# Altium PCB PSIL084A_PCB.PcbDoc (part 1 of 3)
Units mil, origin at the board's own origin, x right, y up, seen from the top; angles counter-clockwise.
Board outline 8750 x 2700 mil, 4 copper layers (Top Layer, Signal Layer 1, Signal Layer 2, Bottom Layer), stack 61.2 mil thick; 274 components, 214 nets, 1279 pads, 354 vias.
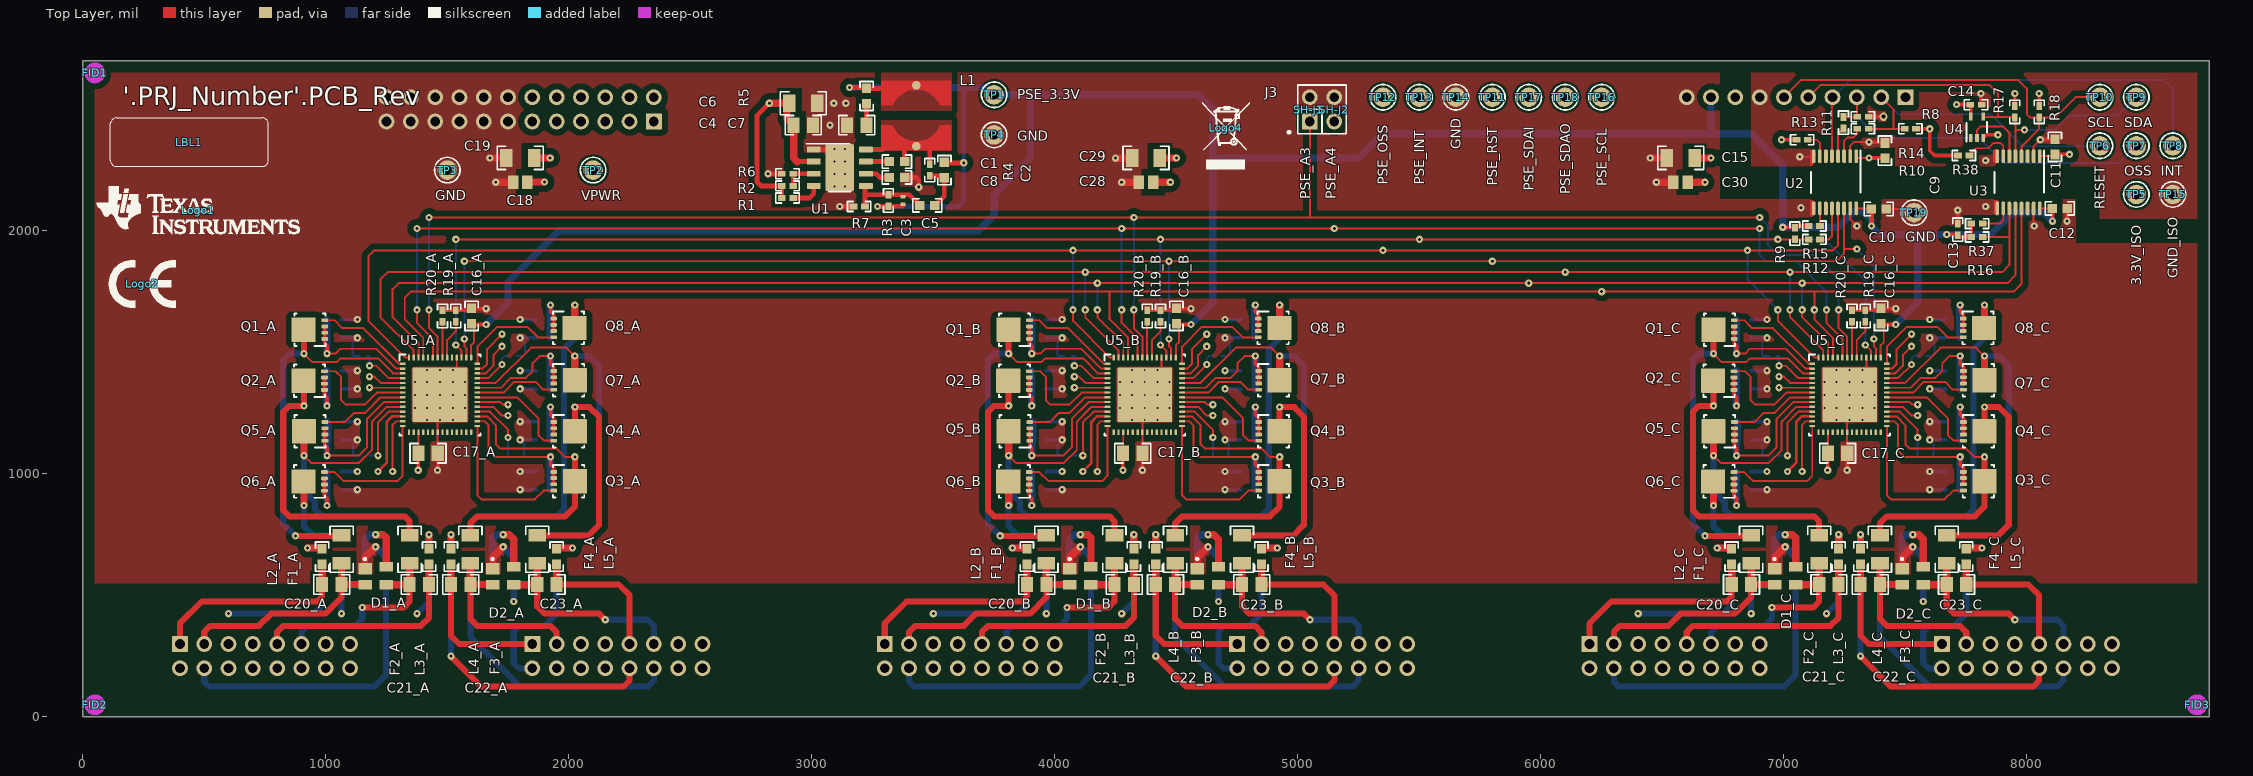
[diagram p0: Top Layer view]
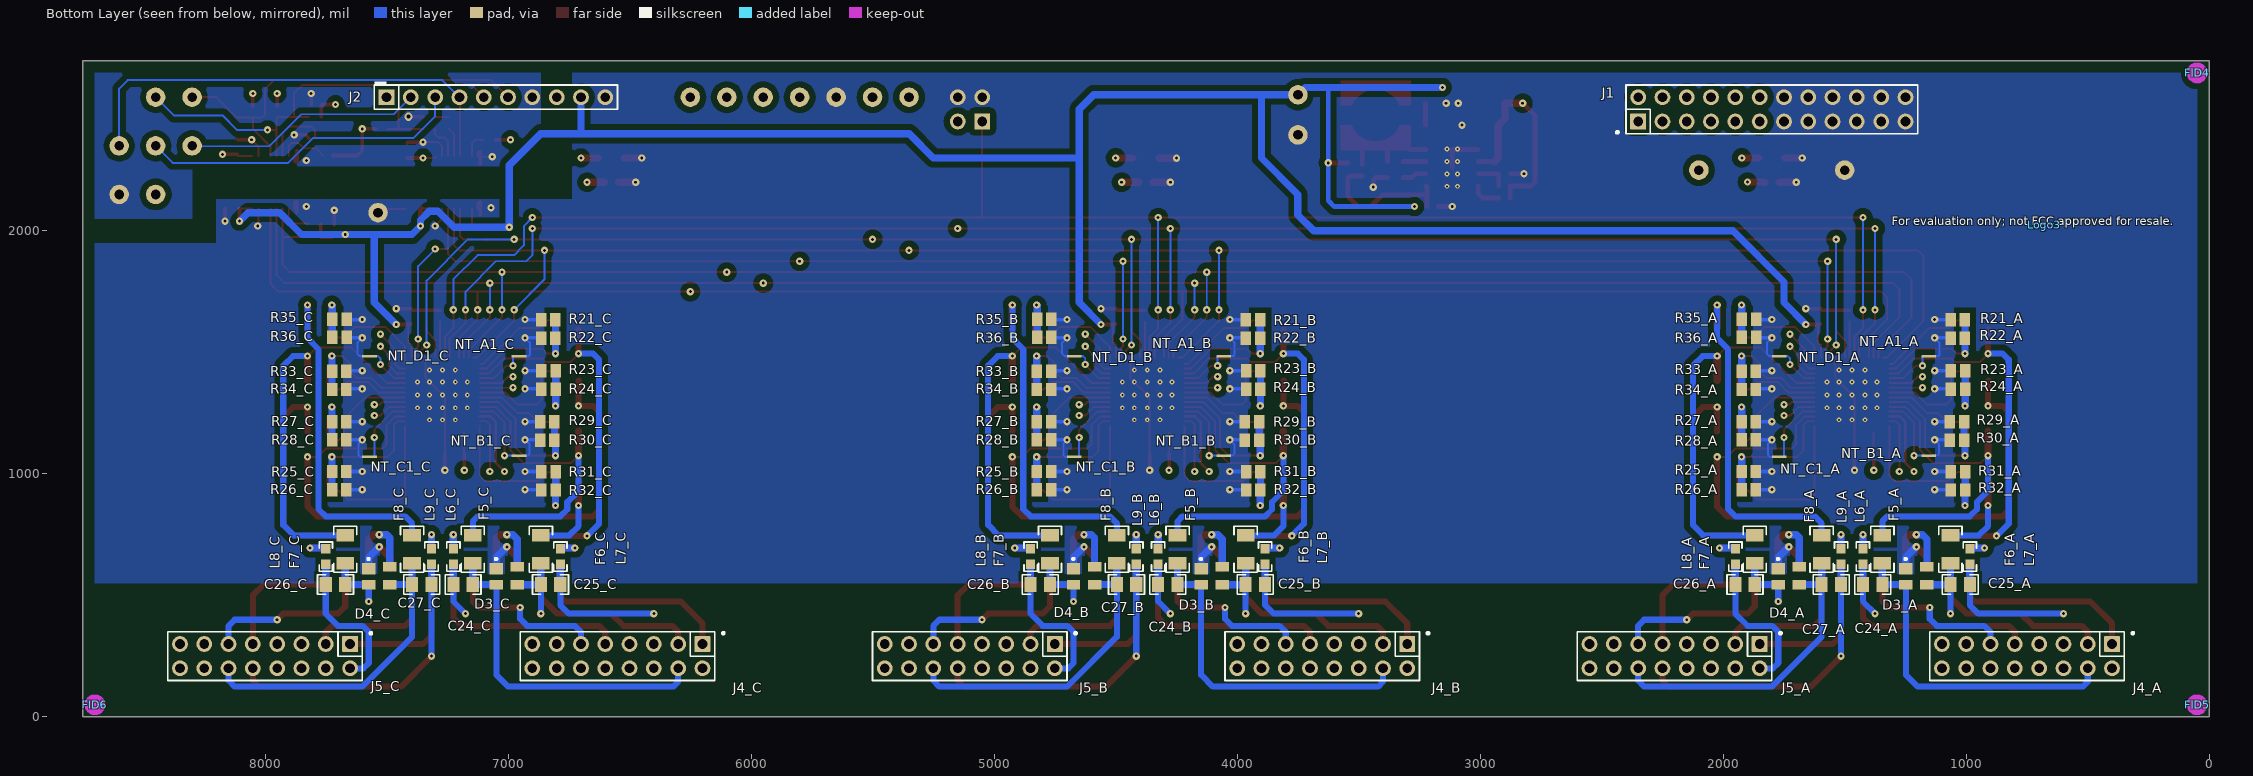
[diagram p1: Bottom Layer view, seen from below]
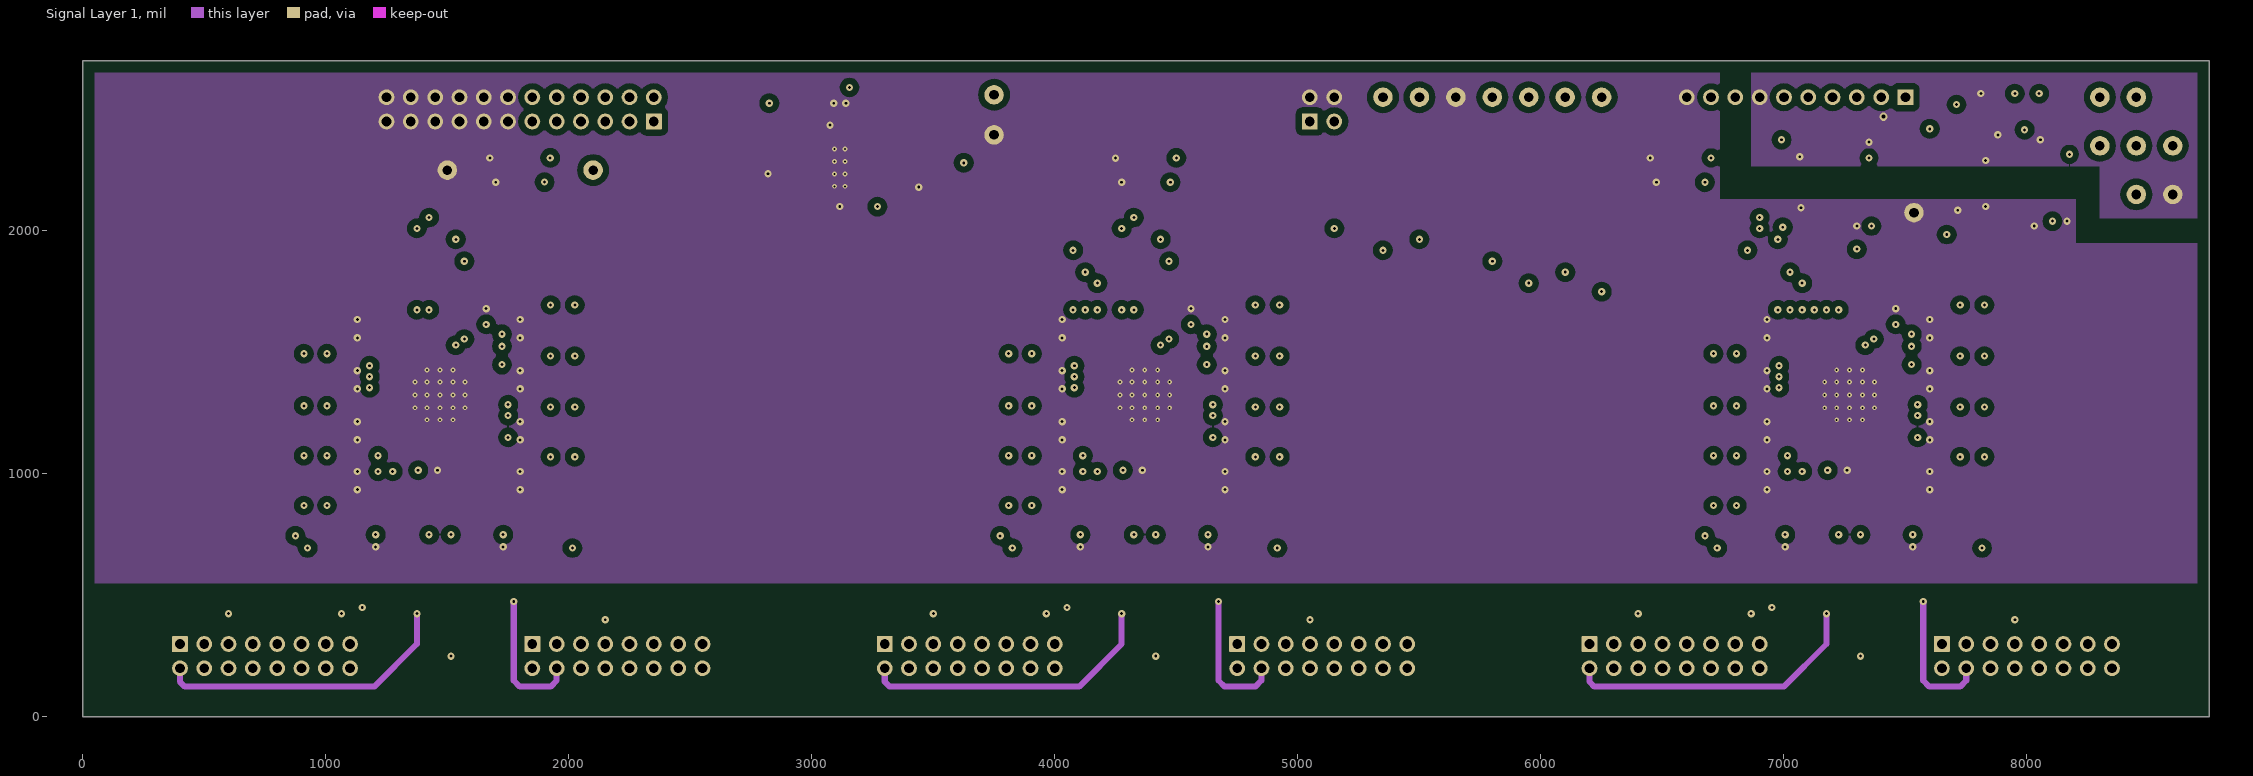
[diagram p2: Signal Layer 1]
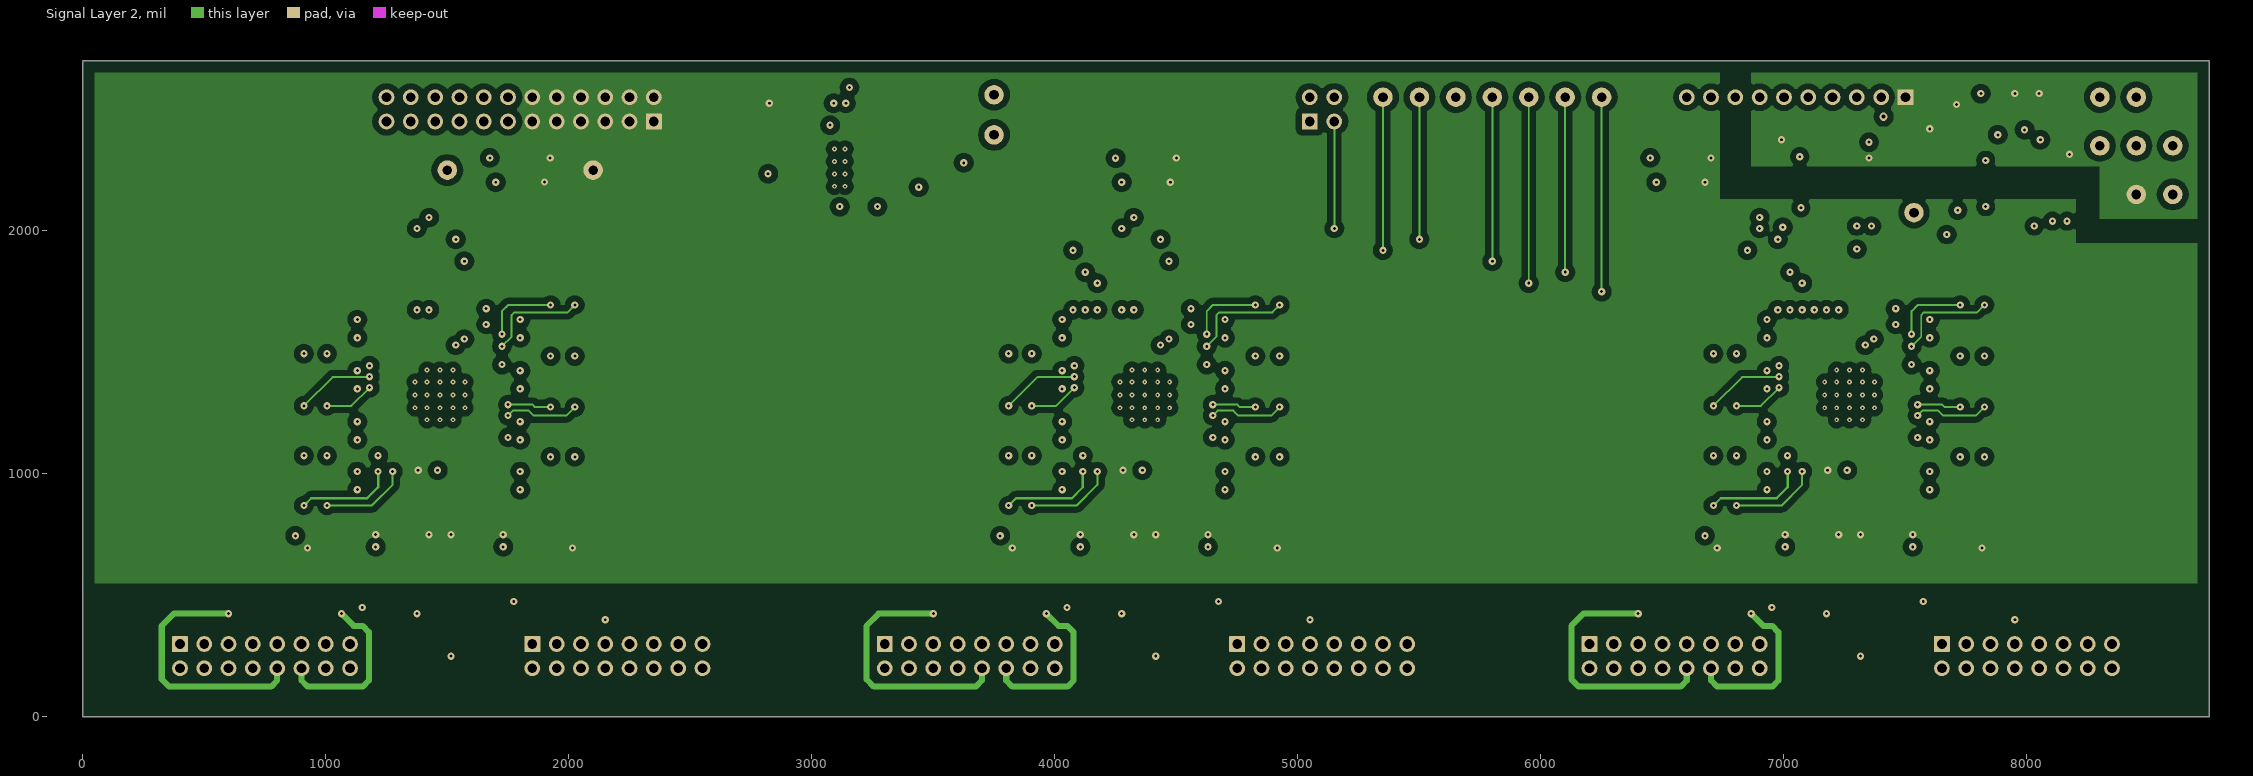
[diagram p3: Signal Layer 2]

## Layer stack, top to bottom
Top Solder: solder mask 0.4, Solder Resist, Dk 3.5
Top Layer: signal copper 2.8
Dielectric1: prepreg 10, FR-4 High TG, Dk 4.2
Signal Layer 1: signal copper 2.8
Dielectric 2: core 30, FR-4 High TG, Dk 4.2
Signal Layer 2: signal copper 2.8
Dielectric 3: prepreg 10, FR-4 High TG, Dk 4.2
Bottom Layer: signal copper 2.8
Bottom Solder: solder mask 0.4, Solder Resist, Dk 3.5

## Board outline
0,0 8750,0 8750,2700 0,2700

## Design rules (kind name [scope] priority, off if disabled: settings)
AcuteAngle [All] p1: minimum=4.50000000000000E+0001 checktracksonly=FALSE
AssemblyTestPointUsage [All] p1: valid=2
BoardOutlineClearance BoardOutlineClearance_MountingHoles [OnCopper and InComponentClass('Mounting Holes')] p1: gap=40 ignorepadtopadclearanceinfootprint=FALSE
BoardOutlineClearance BoardOutlineClearance_Poly [OnCopper and IsPoly] p2: gap=25 ignorepadtopadclearanceinfootprint=FALSE
BoardOutlineClearance [OnCopper and Not InComponentClass('Logo') and not InComponentClass('FiducialMark') and not InRegion(1000,500,4000,800) and not InPoly] p3: gap=75 ignorepadtopadclearanceinfootprint=FALSE
Clearance Clearance_Keepouts [((IsTrack Or IsArc) And Not InPoly) And IsFree and IsKeepOut vs ((IsTrack Or IsArc) And Not InPoly) And IsFree and IsKeepOut] p1: gap=0 ignorepadtopadclearanceinfootprint=FALSE
Clearance Clearance_Poly [InPolygon] p2: gap=25 ignorepadtopadclearanceinfootprint=FALSE except(0: Arc-Hole Track-Hole SMDPad-Hole THPad-Hole Via-Hole Fill-Hole Poly-Hole Region-Hole Text-Hole)
Clearance Clearance_FiducialMark [IsKeepOut and InComponentClass('FiducialMark') vs IsPad and InComponentClass('FiducialMark')] p3: gap=0 ignorepadtopadclearanceinfootprint=FALSE
Clearance [All] p4: gap=7.87 ignorepadtopadclearanceinfootprint=FALSE except(0: Arc-Hole Track-Hole SMDPad-Hole THPad-Hole Via-Hole Fill-Hole Poly-Hole Region-Hole Text-Hole)
ComponentClearance ComponentClearance_MountingHoles_FiducialMarks [InComponentClass('Mounting Holes') vs InComponentClass('FiducialMark')] p1: gap=50 collisioncheckmode=3 verticalgap=10 showdistances=FALSE
ComponentClearance ComponentClearance_Shunt [InComponentClass('Header') or InComponentClass('Shunt') vs InComponentClass('Shunt')] p2: gap=0 collisioncheckmode=3 verticalgap=0 showdistances=FALSE
ComponentClearance ComponentClearance_Logo [InComponentClass('Logo')] p3: gap=50 collisioncheckmode=3 verticalgap=10 showdistances=FALSE
ComponentClearance ComponentClearance_ScrewToNut [(HasFootprint('NY PMS 440 0025 PH')) vs (HasFootprint('Keystone_1902C'))] p4: gap=5 collisioncheckmode=3 verticalgap=10 showdistances=FALSE
ComponentClearance ComponentClearance_MountingHoles [InComponentClass('Mounting Holes')] p5: gap=250 collisioncheckmode=3 verticalgap=100000 showdistances=FALSE
ComponentClearance ComponentClearance_SmallPassives [HasFootprint('0201*') or HasFootprint('0402*') or HasFootprint('0508') or HasFootprint('0603*') or HasFootprint('0612') or HasFootprint('0805*') or HasFootprint('0815*') or HasFootprint('0830*') or HasFootprint('1206*') or HasFootprint('1210*') or HasFootprint('1808*') or HasFootprint('1812*') or HasFootprint('1825*') or HasFootprint('2010*') or HasFootprint('2220*') or HasFootprint('2225*') or HasFootprint('2512*') or HasFootprint('2728*') or HasFootprint('3518*') vs HasFootprint('0201*') or HasFootprint('0402*') or HasFootprint('0508') or HasFootprint('0603*') or HasFootprint('0612') or HasFootprint('0805*') or HasFootprint('0815*') or HasFootprint('0830*') or HasFootprint('1206*') or HasFootprint('1210*') or HasFootprint('1808*') or HasFootprint('1812*') or HasFootprint('1825*') or HasFootprint('2010*') or HasFootprint('2220*') or HasFootprint('2225*') or HasFootprint('2512*') or HasFootprint('2728*') or HasFootprint('3518*')] p6: gap=14.96 collisioncheckmode=3 verticalgap=10 showdistances=FALSE
ComponentClearance ComponentClearance_THtoSMT [IsThruComponent vs IsSMTComponent] p7: gap=40 collisioncheckmode=3 verticalgap=30 showdistances=FALSE
ComponentClearance ComponentClearance_THtoTH [IsThruComponent vs IsThruComponent] p8: gap=30 collisioncheckmode=3 verticalgap=30 showdistances=FALSE
ComponentClearance [All] p9: gap=30 collisioncheckmode=3 verticalgap=10 showdistances=FALSE
DiffPairsRouting [All] p1: maxlimit=100 minlimit=10 mostfreqgap=10 toplayer_minwidth=15 toplayer_maxwidth=15 toplayer_prefwidth=15 midlayer1_minwidth=15 midlayer1_maxwidth=15 midlayer1_prefwidth=15 midlayer2_minwidth=15 midlayer2_maxwidth=15 midlayer2_prefwidth=15 bottomlayer_minwidth=15 bottomlayer_maxwidth=15 bottomlayer_prefwidth=15 maxuncoupledlength=1000
FabricationTestPointUsage TestPointUsage [All] p1: valid=2 allowmultiple=FALSE
FabricationTestpoint Testpoint [All] p1: side=3 testpointundercomponent=TRUE minsize=40 maxsize=100 preferedsize=60 minholesize=0 maxholesize=40 preferedholesize=32 testpointgrid=1 allowsidetop=TRUE allowsidebottom=TRUE usegrid=TRUE gridtolerance=0.01
FanoutControl Fanout_LCC [IsLCC] p1: bgadir=Out bgaviamode=Centered fanoutstyle=Auto fanoutdirection=Alternating viagrid=1 // Fanout_LCC (Default Rule)
FanoutControl Fanout_BGA [IsBGA] p2: bgadir=Out bgaviamode=Centered fanoutstyle=Auto fanoutdirection=Alternating viagrid=1 // Fanout_BGA (Default Rule)
FanoutControl Fanout_Default [All] p4: bgadir=Out bgaviamode=Centered fanoutstyle=Auto fanoutdirection=Alternating viagrid=1 // Fanout_Default (Default Rule)
FanoutControl Fanout_Small [(CompPinCount < 5)] p5: bgadir=Out bgaviamode=Centered fanoutstyle=Auto fanoutdirection=OutThenIn viagrid=1 // Fanout_Small (Default Rule)
Height [All] p1: minheight=0 maxheight=2000 prefheight=500
HoleSize [All] p1: absolutevalues=TRUE maxlimit=251 minlimit=7.87 maxpercent=80.000 minpercent=20.000
MinimumAnnularRing MinimumAnnularRing_ThermalPadVias [IsVia and InAnyComponent] p1: minimumring=5.91
MinimumAnnularRing [All] p2: minimumring=8
MinimumSolderMaskSliver MinimumSolderMaskSliver_Logo [InComponentClass('Logo') vs InComponentClass('Logo')] p1: minsoldermaskwidth=0.7
MinimumSolderMaskSliver [All] p2: minsoldermaskwidth=3.94
PlaneConnect [All] p1: planeconnectstyle=Relief reliefexpansion=10 reliefentries=4 reliefconductorwidth=10 reliefairgap=10
PolygonConnect [All] p1: connectstyle=Direct reliefconductorwidth=10 reliefentries=4 polygonreliefangle="90 Angle" airgapwidth=10
RoomDefinition B [InComponentClass('B')] p1: confinementstyle=ConfineIn formatcopy=TRUE lockcomponents=FALSE outline 3200,100 5550,100 5550,1800 3200,1800
RoomDefinition C [InComponentClass('C')] p2: confinementstyle=ConfineIn formatcopy=TRUE lockcomponents=FALSE outline 6100,100 8450,100 8450,1800 6100,1800
RoomDefinition A [InComponentClass('A')] p3: confinementstyle=ConfineIn formatcopy=TRUE lockcomponents=FALSE outline 300,100 2650,100 2650,1800 300,1800
RoutingVias ThermalPadVias [IsVia and InAnyComponent] p1: holewidth=7.87 width=19.68 viastyle="Through Hole" minholewidth=7.87 minwidth=19.68 maxholewidth=12.99 maxwidth=23.62
RoutingVias [All] p2: holewidth=12 width=30 viastyle="Through Hole" minholewidth=7.87 minwidth=26 maxholewidth=40 maxwidth=65
SilkToBoardRegionClearance [Not ((IsComment or IsDesignator) And (Hide <> 'False')) and not InRegion(1000,500,4000,800)] p1:
SilkToSilkClearance SilkToSilkClearance_Pb-FreeLogo [(HasFootprint('Pb-Free_Overlay_Medium') OR HasFootprint('Pb-Free_Overlay_Small')) vs (HasFootprint('Pb-Free_Overlay_Medium') OR HasFootprint('Pb-Free_Overlay_Small'))] p1: silktosilkclearance=0
SilkToSilkClearance [All] p2: silktosilkclearance=4
SilkToSolderMaskClearance SilkToComponentPadClearance [(IsPad or IsFill or IsRegion) and InAnycomponent] p1: minsilkscreentomaskgap=5 clearancetoexposedcopper=TRUE
SilkToSolderMaskClearance "Silk to Solder Mask Opening" [All] p2: minsilkscreentomaskgap=4 clearancetoexposedcopper=FALSE
SolderMaskExpansion [All] p1: expansion=1.97
Width [All] p1: maxlimit=100 minlimit=6 preferedwidth=10 checkconnectedcopper=TRUE
14 further rules are at their usual default settings.

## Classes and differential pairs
channel class PSIL084A_SH2: A B C
component class U_PSIL084A_EVM_Hardware: !PCB FID1 FID2 FID3 FID4 FID5 FID6 LBL1 Logo1 Logo2 Logo3 Logo4 SH-J1 SH-J2 ZZ1 ZZ2 ZZ3 ZZ4 ZZ5
component class Logo: Logo1
component class Label: LBL1
component class FiducialMark: FID1 FID2 FID3 FID4 FID5 FID6
component class AssemblyNote: ZZ1 ZZ2 ZZ3 ZZ4 ZZ5
component class A: C16_A C17_A C20_A C21_A C22_A C23_A C24_A C25_A C26_A C27_A D1_A D2_A D3_A D4_A F1_A F2_A F3_A F4_A F5_A F6_A F7_A F8_A J4_A J5_A L2_A L3_A L4_A L5_A L6_A L7_A L8_A L9_A NT_A1_A NT_B1_A NT_C1_A NT_D1_A Q1_A Q2_A Q3_A Q4_A Q5_A Q6_A Q7_A Q8_A R19_A R20_A R21_A R22_A R23_A R24_A R25_A R26_A R27_A R28_A R29_A R30_A R31_A R32_A R33_A R34_A R35_A R36_A U5_A
component class B: C16_B C17_B C20_B C21_B C22_B C23_B C24_B C25_B C26_B C27_B D1_B D2_B D3_B D4_B F1_B F2_B F3_B F4_B F5_B F6_B F7_B F8_B J4_B J5_B L2_B L3_B L4_B L5_B L6_B L7_B L8_B L9_B NT_A1_B NT_B1_B NT_C1_B NT_D1_B Q1_B Q2_B Q3_B Q4_B Q5_B Q6_B Q7_B Q8_B R19_B R20_B R21_B R22_B R23_B R24_B R25_B R26_B R27_B R28_B R29_B R30_B R31_B R32_B R33_B R34_B R35_B R36_B U5_B
component class C: C16_C C17_C C20_C C21_C C22_C C23_C C24_C C25_C C26_C C27_C D1_C D2_C D3_C D4_C F1_C F2_C F3_C F4_C F5_C F6_C F7_C F8_C J4_C J5_C L2_C L3_C L4_C L5_C L6_C L7_C L8_C L9_C NT_A1_C NT_B1_C NT_C1_C NT_D1_C Q1_C Q2_C Q3_C Q4_C Q5_C Q6_C Q7_C Q8_C R19_C R20_C R21_C R22_C R23_C R24_C R25_C R26_C R27_C R28_C R29_C R30_C R31_C R32_C R33_C R34_C R35_C R36_C U5_C
component class Header: J1 J2 J3 J4_A J4_B J4_C J5_A J5_B J5_C
component class PSIL084A_SH1: C1 C2 C3 C4 C5 C6 C7 C8 C9 C10 C11 C12 C13 C14 C15 C18 C19 C28 C29 C30 J1 J2 J3 L1 R1 R2 R3 R4 R5 R6 R7 R8 R9 R10 R11 R12 R13 R14 R15 R16 R17 R18 R37 R38 TP1 TP2 TP3 TP4 TP5 TP6 TP7 TP8 TP9 TP10 TP11 TP12 TP13 TP14 TP15 TP16 TP17 TP18 TP19 U1 U2 U3 U4
component class Shunt: SH-J1 SH-J2

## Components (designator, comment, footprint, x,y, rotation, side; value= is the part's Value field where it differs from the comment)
C1 "885012206089" 0603 3350,2285 r180 top value=0.01uF
C2 "GRM1885C1H332JA01D" 0603 3545,2250 r270 top value=3300pF
C3 "GCM1555C1H121FA16D" FP-GCM1555C1H121FA16D_0402-MFG 3375,2125 r90 top
C4 "C2012X7R2A104K125AA" 0805_HV 2965,2435 r180 top value=0.1uF
C5 "885012206095" 0603 3475,2105 r180 top value=0.1uF
C6 "GCJ31CR72A105KA01K" 1206 2965,2525 r180 top value=1uF
C7 "885012207026" 0805_HV 3185,2435 r180 top value=10uF
C8 "CL10B105MO8NNWC" 0603 3350,2220 r0 top value=1uF
C9 "885012206095" 0603 7415,2330 r90 top value=0.1uF
C10 "885012206095" 0603 7390,2090 r0 top value=0.1uF
C11 "885012206095" 0603 8115,2345.67 r90 top value=0.1uF
C12 "885012206095" 0603 8135,2092.72 r0 top value=0.1uF
C13 "885012205031" 0402 7715,2005 r270 top value=0.01uF
C14 "885012205031" 0402 7790,2518.99 r180 top value=0.01uF
C15 "GCJ31CR72A105KA01K" 1206 6575,2300 r0 top value=1uF
C16_A "885012206095" 0603 1600,1650 r90 top value=0.1uF (schematic designator C16)
C16_B "885012206095" 0603 4500,1650 r90 top value=0.1uF (schematic designator C16)
C16_C "885012206095" 0603 7400,1650 r90 top value=0.1uF (schematic designator C16)
C17_A "C2012X7R2A104K125AA" 0805_HV 1420.79,1085 r0 top value=0.1uF (schematic designator C17)
C17_B "C2012X7R2A104K125AA" 0805_HV 4320.79,1085 r0 top value=0.1uF (schematic designator C17)
C17_C "C2012X7R2A104K125AA" 0805_HV 7220.79,1085 r0 top value=0.1uF (schematic designator C17)
C18 "C2012X7R2A104K125AA" 0805L 1800,2200 r0 top value=0.1uF
C19 "GCJ31CR72A105KA01K" 1206 1800,2300 r0 top value=1uF
C20_A "C2012X7R2A104K125AA" 0805_HV 1025,545 r0 top value=0.1uF (schematic designator C20)
C20_B "C2012X7R2A104K125AA" 0805_HV 3925,545 r0 top value=0.1uF (schematic designator C20)
C20_C "C2012X7R2A104K125AA" 0805_HV 6825,545 r0 top value=0.1uF (schematic designator C20)
C21_A "C2012X7R2A104K125AA" 0805_HV 1385,545 r180 top value=0.1uF (schematic designator C21)
C21_B "C2012X7R2A104K125AA" 0805_HV 4285,545 r180 top value=0.1uF (schematic designator C21)
C21_C "C2012X7R2A104K125AA" 0805_HV 7185,545 r180 top value=0.1uF (schematic designator C21)
C22_A "C2012X7R2A104K125AA" 0805_HV 1555,545 r0 top value=0.1uF (schematic designator C22)
C22_B "C2012X7R2A104K125AA" 0805_HV 4455,545 r0 top value=0.1uF (schematic designator C22)
C22_C "C2012X7R2A104K125AA" 0805_HV 7355,545 r0 top value=0.1uF (schematic designator C22)
C23_A "C2012X7R2A104K125AA" 0805_HV 1910,545 r180 top value=0.1uF (schematic designator C23)
C23_B "C2012X7R2A104K125AA" 0805_HV 4810,545 r180 top value=0.1uF (schematic designator C23)
C23_C "C2012X7R2A104K125AA" 0805_HV 7710,545 r180 top value=0.1uF (schematic designator C23)
C24_A "C2012X7R2A104K125AA" 0805_HV 1385,545 r180 bottom value=0.1uF (schematic designator C24)
C24_B "C2012X7R2A104K125AA" 0805_HV 4285,545 r180 bottom value=0.1uF (schematic designator C24)
C24_C "C2012X7R2A104K125AA" 0805_HV 7185,545 r180 bottom value=0.1uF (schematic designator C24)
C25_A "C2012X7R2A104K125AA" 0805_HV 1025,545 r0 bottom value=0.1uF (schematic designator C25)
C25_B "C2012X7R2A104K125AA" 0805_HV 3925,545 r0 bottom value=0.1uF (schematic designator C25)
C25_C "C2012X7R2A104K125AA" 0805_HV 6825,545 r0 bottom value=0.1uF (schematic designator C25)
C26_A "C2012X7R2A104K125AA" 0805_HV 1910,545 r180 bottom value=0.1uF (schematic designator C26)
C26_B "C2012X7R2A104K125AA" 0805_HV 4810,545 r180 bottom value=0.1uF (schematic designator C26)
C26_C "C2012X7R2A104K125AA" 0805_HV 7710,545 r180 bottom value=0.1uF (schematic designator C26)
C27_A "C2012X7R2A104K125AA" 0805_HV 1555,545 r0 bottom value=0.1uF (schematic designator C27)
C27_B "C2012X7R2A104K125AA" 0805_HV 4455,545 r0 bottom value=0.1uF (schematic designator C27)
C27_C "C2012X7R2A104K125AA" 0805_HV 7355,545 r0 bottom value=0.1uF (schematic designator C27)
C28 "C2012X7R2A104K125AA" 0805L 4375,2200 r0 top value=0.1uF
C29 "GCJ31CR72A105KA01K" 1206 4375,2300 r0 top value=1uF
C30 "C2012X7R2A104K125AA" 0805L 6575,2200 r0 top value=0.1uF
D1_A "CD143A-SR70" SOT-143-4 1205,575 r0 top value=7V (schematic designator D1)
D1_B "CD143A-SR70" SOT-143-4 4105,575 r0 top value=7V (schematic designator D1)
D1_C "CD143A-SR70" SOT-143-4 7005,575 r0 top value=7V (schematic designator D1)
D2_A "CD143A-SR70" SOT-143-4 1730,575 r0 top value=7V (schematic designator D2)
D2_B "CD143A-SR70" SOT-143-4 4630,575 r0 top value=7V (schematic designator D2)
D2_C "CD143A-SR70" SOT-143-4 7530,575 r0 top value=7V (schematic designator D2)
D3_A "CD143A-SR70" SOT-143-4 1205,575 r180 bottom value=7V (schematic designator D3)
D3_B "CD143A-SR70" SOT-143-4 4105,575 r180 bottom value=7V (schematic designator D3)
D3_C "CD143A-SR70" SOT-143-4 7005,575 r180 bottom value=7V (schematic designator D3)
D4_A "CD143A-SR70" SOT-143-4 1730,575 r180 bottom value=7V (schematic designator D4)
D4_B "CD143A-SR70" SOT-143-4 4630,575 r180 bottom value=7V (schematic designator D4)
D4_C "CD143A-SR70" SOT-143-4 7530,575 r180 bottom value=7V (schematic designator D4)
F1_A "C1S 1.5" 1206 1065,690 r90 top (schematic designator F1)
F1_B "C1S 1.5" 1206 3965,690 r90 top (schematic designator F1)
F1_C "C1S 1.5" 1206 6865,690 r90 top (schematic designator F1)
F2_A "C1S 1.5" 1206 1345,690 r90 top (schematic designator F2)
F2_B "C1S 1.5" 1206 4245,690 r90 top (schematic designator F2)
F2_C "C1S 1.5" 1206 7145,690 r90 top (schematic designator F2)
F3_A "C1S 1.5" 1206 1595,690 r90 top (schematic designator F3)
F3_B "C1S 1.5" 1206 4495,690 r90 top (schematic designator F3)
F3_C "C1S 1.5" 1206 7395,690 r90 top (schematic designator F3)
F4_A "C1S 1.5" 1206 1870,690 r90 top (schematic designator F4)
F4_B "C1S 1.5" 1206 4770,690 r90 top (schematic designator F4)
F4_C "C1S 1.5" 1206 7670,690 r90 top (schematic designator F4)
F5_A "C1S 1.5" 1206 1345,690 r90 bottom (schematic designator F5)
F5_B "C1S 1.5" 1206 4245,690 r90 bottom (schematic designator F5)
F5_C "C1S 1.5" 1206 7145,690 r90 bottom (schematic designator F5)
F6_A "C1S 1.5" 1206 1065,690 r90 bottom (schematic designator F6)
F6_B "C1S 1.5" 1206 3965,690 r90 bottom (schematic designator F6)
F6_C "C1S 1.5" 1206 6865,690 r90 bottom (schematic designator F6)
F7_A "C1S 1.5" 1206 1870,690 r90 bottom (schematic designator F7)
F7_B "C1S 1.5" 1206 4770,690 r90 bottom (schematic designator F7)
F7_C "C1S 1.5" 1206 7670,690 r90 bottom (schematic designator F7)
F8_A "C1S 1.5" 1206 1595,690 r90 bottom (schematic designator F8)
F8_B "C1S 1.5" 1206 4495,690 r90 bottom (schematic designator F8)
F8_C "C1S 1.5" 1206 7395,690 r90 bottom (schematic designator F8)
FID1 "Fiducial" Fiducial10-20 50,2650 r0 top
FID2 "Fiducial" Fiducial10-20 50,50 r0 top
FID3 "Fiducial" Fiducial10-20 8700,50 r0 top
FID4 "Fiducial" Fiducial10-20 50,2650 r180 bottom
FID5 "Fiducial" Fiducial10-20 50,50 r180 bottom
FID6 "Fiducial" Fiducial10-20 8700,50 r180 bottom
J1 "TSW-112-07-G-D" TSW-112-07-G-D 1800,2500 r180 bottom locked
J2 "TSW-110-07-G-S" TSW-110-07-G-S 7050,2550 r180 bottom locked
J3 "TSW-102-07-G-D" TSW-102-07-G-D 5099.16,2500.21 r0 top
J4_A "TSW-108-09-G-D" TSW-108-07-G-D 750,250 r0 bottom (schematic designator J4)
J4_B "TSW-108-09-G-D" TSW-108-07-G-D 3650,250 r0 bottom (schematic designator J4)
J4_C "TSW-108-09-G-D" TSW-108-07-G-D 6550,250 r0 bottom (schematic designator J4)
J5_A "TSW-108-09-G-D" TSW-108-07-G-D 2200,250 r0 bottom (schematic designator J5)
J5_B "TSW-108-09-G-D" TSW-108-07-G-D 5100,250 r0 bottom (schematic designator J5)
J5_C "TSW-108-09-G-D" TSW-108-07-G-D 8000,250 r0 bottom (schematic designator J5)
L1 "744062151" WE-TPC_6823 3430,2475 r180 top value=150uH
L2_A "MPZ1608S601ATD25" 0603 985,660 r270 top value="600 ohm" (schematic designator L2)
L2_B "MPZ1608S601ATD25" 0603 3885,660 r270 top value="600 ohm" (schematic designator L2)
L2_C "MPZ1608S601ATD25" 0603 6785,660 r270 top value="600 ohm" (schematic designator L2)
L3_A "MPZ1608S601ATD25" 0603 1425,660 r270 top value="600 ohm" (schematic designator L3)
L3_B "MPZ1608S601ATD25" 0603 4325,660 r270 top value="600 ohm" (schematic designator L3)
L3_C "MPZ1608S601ATD25" 0603 7225,660 r270 top value="600 ohm" (schematic designator L3)
L4_A "MPZ1608S601ATD25" 0603 1515,660 r270 top value="600 ohm" (schematic designator L4)
L4_B "MPZ1608S601ATD25" 0603 4415,660 r270 top value="600 ohm" (schematic designator L4)
L4_C "MPZ1608S601ATD25" 0603 7315,660 r270 top value="600 ohm" (schematic designator L4)
L5_A "MPZ1608S601ATD25" 0603 1950,660 r270 top value="600 ohm" (schematic designator L5)
L5_B "MPZ1608S601ATD25" 0603 4850,660 r270 top value="600 ohm" (schematic designator L5)
L5_C "MPZ1608S601ATD25" 0603 7750,660 r270 top value="600 ohm" (schematic designator L5)
L6_A "MPZ1608S601ATD25" 0603 1425,660 r270 bottom value="600 ohm" (schematic designator L6)
L6_B "MPZ1608S601ATD25" 0603 4325,660 r270 bottom value="600 ohm" (schematic designator L6)
L6_C "MPZ1608S601ATD25" 0603 7225,660 r270 bottom value="600 ohm" (schematic designator L6)
L7_A "MPZ1608S601ATD25" 0603 985,660 r270 bottom value="600 ohm" (schematic designator L7)
L7_B "MPZ1608S601ATD25" 0603 3885,660 r270 bottom value="600 ohm" (schematic designator L7)
L7_C "MPZ1608S601ATD25" 0603 6785,660 r270 bottom value="600 ohm" (schematic designator L7)
L8_A "MPZ1608S601ATD25" 0603 1950,660 r270 bottom value="600 ohm" (schematic designator L8)
L8_B "MPZ1608S601ATD25" 0603 4850,660 r270 bottom value="600 ohm" (schematic designator L8)
L8_C "MPZ1608S601ATD25" 0603 7750,660 r270 bottom value="600 ohm" (schematic designator L8)
L9_A "MPZ1608S601ATD25" 0603 1515,660 r270 bottom value="600 ohm" (schematic designator L9)
L9_B "MPZ1608S601ATD25" 0603 4415,660 r270 bottom value="600 ohm" (schematic designator L9)
L9_C "MPZ1608S601ATD25" 0603 7315,660 r270 bottom value="600 ohm" (schematic designator L9)
LBL1 "THT-14-423-10" Label_650x200 438.65,2365 r0 top
Logo1 "Texas Instruments" TI_Stacked_Overlay_Small 475,2085 r0 top
Logo2 "CE Mark" CE_Mark_5mm 245,1781.79 r0 top
Logo3 "FCC disclaimer" FCC_disclaimer 679.02,2025 r180 bottom
Logo4 "WEEE logo" WEEE_Minimum 4702.17,2425 r0 top
NT_A1_A "Net-Tie" Net-Tie_10milWide_30milLong 1155,1485 r0 bottom net-tie (schematic designator NT_A1)
NT_A1_B "Net-Tie" Net-Tie_10milWide_30milLong 4055,1485 r0 bottom net-tie (schematic designator NT_A1)
NT_A1_C "Net-Tie" Net-Tie_10milWide_30milLong 6955,1485 r0 bottom net-tie (schematic designator NT_A1)
NT_B1_A "Net-Tie" Net-Tie_10milWide_30milLong 1155,1075 r180 bottom net-tie (schematic designator NT_B1)
NT_B1_B "Net-Tie" Net-Tie_10milWide_30milLong 4055,1075 r180 bottom net-tie (schematic designator NT_B1)
NT_B1_C "Net-Tie" Net-Tie_10milWide_30milLong 6955,1075 r180 bottom net-tie (schematic designator NT_B1)
NT_C1_A "Net-Tie" Net-Tie_10milWide_30milLong 1770,1070 r0 bottom net-tie (schematic designator NT_C1)
NT_C1_B "Net-Tie" Net-Tie_10milWide_30milLong 4670,1070 r0 bottom net-tie (schematic designator NT_C1)
NT_C1_C "Net-Tie" Net-Tie_10milWide_30milLong 7570,1070 r0 bottom net-tie (schematic designator NT_C1)
NT_D1_A "Net-Tie" Net-Tie_10milWide_30milLong 1770,1485 r0 bottom net-tie (schematic designator NT_D1)
NT_D1_B "Net-Tie" Net-Tie_10milWide_30milLong 4670,1485 r0 bottom net-tie (schematic designator NT_D1)
NT_D1_C "Net-Tie" Net-Tie_10milWide_30milLong 7570,1485 r0 bottom net-tie (schematic designator NT_D1)
Q1_A "CSD19538Q3A" DNH0008A_NV 934.67,1593.92 r180 top value=100V (schematic designator Q1)
Q1_B "CSD19538Q3A" DNH0008A_NV 3834.67,1593.92 r180 top value=100V (schematic designator Q1)
Q1_C "CSD19538Q3A" DNH0008A_NV 6734.67,1593.92 r180 top value=100V (schematic designator Q1)
Q2_A "CSD19538Q3A" DNH0008A_NV 933.56,1383.92 r180 top value=100V (schematic designator Q2)
Q2_B "CSD19538Q3A" DNH0008A_NV 3833.56,1383.92 r180 top value=100V (schematic designator Q2)
Q2_C "CSD19538Q3A" DNH0008A_NV 6733.56,1383.92 r180 top value=100V (schematic designator Q2)
Q3_A "CSD19538Q3A" DNH0008A_NV 1999.61,970 r0 top value=100V (schematic designator Q3)
Q3_B "CSD19538Q3A" DNH0008A_NV 4899.61,970 r0 top value=100V (schematic designator Q3)
Q3_C "CSD19538Q3A" DNH0008A_NV 7799.61,970 r0 top value=100V (schematic designator Q3)
Q4_A "CSD19538Q3A" DNH0008A_NV 1999.61,1175 r0 top value=100V (schematic designator Q4)
Q4_B "CSD19538Q3A" DNH0008A_NV 4899.61,1175 r0 top value=100V (schematic designator Q4)
Q4_C "CSD19538Q3A" DNH0008A_NV 7799.61,1175 r0 top value=100V (schematic designator Q4)
Q5_A "CSD19538Q3A" DNH0008A_NV 935.39,1175 r180 top value=100V (schematic designator Q5)
Q5_B "CSD19538Q3A" DNH0008A_NV 3835.39,1175 r180 top value=100V (schematic designator Q5)
Q5_C "CSD19538Q3A" DNH0008A_NV 6735.39,1175 r180 top value=100V (schematic designator Q5)
Q6_A "CSD19538Q3A" DNH0008A_NV 933.56,968.92 r180 top value=100V (schematic designator Q6)
Q6_B "CSD19538Q3A" DNH0008A_NV 3833.56,968.92 r180 top value=100V (schematic designator Q6)
Q6_C "CSD19538Q3A" DNH0008A_NV 6733.56,968.92 r180 top value=100V (schematic designator Q6)
Q7_A "CSD19538Q3A" DNH0008A_NV 1999.61,1385 r0 top value=100V (schematic designator Q7)
Q7_B "CSD19538Q3A" DNH0008A_NV 4899.61,1385 r0 top value=100V (schematic designator Q7)
Q7_C "CSD19538Q3A" DNH0008A_NV 7799.61,1385 r0 top value=100V (schematic designator Q7)
Q8_A "CSD19538Q3A" DNH0008A_NV 1998.5,1600.48 r0 top value=100V (schematic designator Q8)
Q8_B "CSD19538Q3A" DNH0008A_NV 4898.5,1600.48 r0 top value=100V (schematic designator Q8)
Q8_C "CSD19538Q3A" DNH0008A_NV 7798.5,1600.48 r0 top value=100V (schematic designator Q8)
R1 "CRCW0402150KFKED" 0402 2900,2135 r0 top value=150k
R2 "CRCW0402100KFKED" 0402 2900,2185 r0 top value=100k
R3 "CRCW040210K0FKED" 0402 3315,2125 r90 top value=10.0k
R4 "CRCW0402133KFKED" 0402 3485,2250 r270 top value=133k
R5 "RC0603JR-070RL" 0603 3225,2555 r270 top value=0
R6 "CRCW04023K92FKED" 0402 2900,2235 r180 top value=3.92k
R7 "CRCW04026K04FKED" 0402 3195,2100 r180 top value=6.04k
R8 "CRCW040210K0FKED" 0402 7520,2420 r180 top value=10.0k
R9 "CRCW04024K70JNED" 0402 7045,1988.62 r90 top value=4.7k
R10 "ERJ-2GE0R00X" 0402 7325,2420 r180 top value=0
R11 "ERJ-2GE0R00X" 0402 7245,2445 r270 top value=0
R12 "ERJ-2GE0R00X" 0402 7125,1965 r180 top value=0
R13 "CRCW04024K70JNED" 0402 7075,2375 r180 top value=4.7k
R14 "CRCW040210K0FKED" 0402 7325,2470 r0 top value=10.0k
R15 "CRCW04024K70JNED" 0402 7125,2020 r0 top value=4.7k
R16 "CRCW04024K70JNED" 0402 7795,1975 r180 top value=4.7k
R17 "CRCW040210K0FKED" 0402 7950,2490 r270 top value=10.0k
R18 "CRCW040210K0FKED" 0402 8050,2490 r270 top value=10.0k
R19_A "ERJ-2GE0R00X" 0402 1535,1650 r90 top value=0 (schematic designator R19)
R19_B "ERJ-2GE0R00X" 0402 4435,1650 r90 top value=0 (schematic designator R19)
R19_C "ERJ-2GE0R00X" 0402 7335,1650 r90 top value=0 (schematic designator R19)
R20_A "ERJ-2GE0R00X" 0402 1480,1650 r90 top value=0 (schematic designator R20)
R20_B "ERJ-2GE0R00X" 0402 4380,1650 r90 top value=0 (schematic designator R20)
R20_C "ERJ-2GE0R00X" 0402 7280,1650 r90 top value=0 (schematic designator R20)
R21_A "CRM0805-FX-R510ELF" 0805L 1034.67,1633.92 r0 bottom value=0.51 (schematic designator R21)
R21_B "CRM0805-FX-R510ELF" 0805L 3934.67,1633.92 r0 bottom value=0.51 (schematic designator R21)
R21_C "CRM0805-FX-R510ELF" 0805L 6834.67,1633.92 r0 bottom value=0.51 (schematic designator R21)
R22_A "CRM0805-FX-R510ELF" 0805L 1034.67,1558.92 r0 bottom value=0.51 (schematic designator R22)
R22_B "CRM0805-FX-R510ELF" 0805L 3934.67,1558.92 r0 bottom value=0.51 (schematic designator R22)
R22_C "CRM0805-FX-R510ELF" 0805L 6834.67,1558.92 r0 bottom value=0.51 (schematic designator R22)
R23_A "CRM0805-FX-R510ELF" 0805L 1033.56,1423.92 r0 bottom value=0.51 (schematic designator R23)
R23_B "CRM0805-FX-R510ELF" 0805L 3933.56,1423.92 r0 bottom value=0.51 (schematic designator R23)
R23_C "CRM0805-FX-R510ELF" 0805L 6833.56,1423.92 r0 bottom value=0.51 (schematic designator R23)
R24_A "CRM0805-FX-R510ELF" 0805L 1033.56,1348.92 r0 bottom value=0.51 (schematic designator R24)
R24_B "CRM0805-FX-R510ELF" 0805L 3933.56,1348.92 r0 bottom value=0.51 (schematic designator R24)
R24_C "CRM0805-FX-R510ELF" 0805L 6833.56,1348.92 r0 bottom value=0.51 (schematic designator R24)
R25_A "CRM0805-FX-R510ELF" 0805L 1894.61,1010 r180 bottom value=0.51 (schematic designator R25)
R25_B "CRM0805-FX-R510ELF" 0805L 4794.61,1010 r180 bottom value=0.51 (schematic designator R25)
R25_C "CRM0805-FX-R510ELF" 0805L 7694.61,1010 r180 bottom value=0.51 (schematic designator R25)
R26_A "CRM0805-FX-R510ELF" 0805L 1894.61,935 r180 bottom value=0.51 (schematic designator R26)
R26_B "CRM0805-FX-R510ELF" 0805L 4794.61,935 r180 bottom value=0.51 (schematic designator R26)
R26_C "CRM0805-FX-R510ELF" 0805L 7694.61,935 r180 bottom value=0.51 (schematic designator R26)
R27_A "CRM0805-FX-R510ELF" 0805L 1894.61,1215 r180 bottom value=0.51 (schematic designator R27)
R27_B "CRM0805-FX-R510ELF" 0805L 4794.61,1215 r180 bottom value=0.51 (schematic designator R27)
R27_C "CRM0805-FX-R510ELF" 0805L 7694.61,1215 r180 bottom value=0.51 (schematic designator R27)
R28_A "CRM0805-FX-R510ELF" 0805L 1894.61,1140 r180 bottom value=0.51 (schematic designator R28)
R28_B "CRM0805-FX-R510ELF" 0805L 4794.61,1140 r180 bottom value=0.51 (schematic designator R28)
R28_C "CRM0805-FX-R510ELF" 0805L 7694.61,1140 r180 bottom value=0.51 (schematic designator R28)
R29_A "CRM0805-FX-R510ELF" 0805L 1038.56,1213.92 r0 bottom value=0.51 (schematic designator R29)
R29_B "CRM0805-FX-R510ELF" 0805L 3938.56,1213.92 r0 bottom value=0.51 (schematic designator R29)
R29_C "CRM0805-FX-R510ELF" 0805L 6838.56,1213.92 r0 bottom value=0.51 (schematic designator R29)
R30_A "CRM0805-FX-R510ELF" 0805L 1038.56,1138.92 r0 bottom value=0.51 (schematic designator R30)
R30_B "CRM0805-FX-R510ELF" 0805L 3938.56,1138.92 r0 bottom value=0.51 (schematic designator R30)
R30_C "CRM0805-FX-R510ELF" 0805L 6838.56,1138.92 r0 bottom value=0.51 (schematic designator R30)
R31_A "CRM0805-FX-R510ELF" 0805L 1033.56,1008.92 r0 bottom value=0.51 (schematic designator R31)
R31_B "CRM0805-FX-R510ELF" 0805L 3933.56,1008.92 r0 bottom value=0.51 (schematic designator R31)
R31_C "CRM0805-FX-R510ELF" 0805L 6833.56,1008.92 r0 bottom value=0.51 (schematic designator R31)
R32_A "CRM0805-FX-R510ELF" 0805L 1033.56,933.92 r0 bottom value=0.51 (schematic designator R32)
R32_B "CRM0805-FX-R510ELF" 0805L 3933.56,933.92 r0 bottom value=0.51 (schematic designator R32)
R32_C "CRM0805-FX-R510ELF" 0805L 6833.56,933.92 r0 bottom value=0.51 (schematic designator R32)
R33_A "CRM0805-FX-R510ELF" 0805L 1894.61,1422.39 r180 bottom value=0.51 (schematic designator R33)
R33_B "CRM0805-FX-R510ELF" 0805L 4794.61,1422.39 r180 bottom value=0.51 (schematic designator R33)
R33_C "CRM0805-FX-R510ELF" 0805L 7694.61,1422.39 r180 bottom value=0.51 (schematic designator R33)
R34_A "CRM0805-FX-R510ELF" 0805L 1894.61,1347.39 r180 bottom value=0.51 (schematic designator R34)
R34_B "CRM0805-FX-R510ELF" 0805L 4794.61,1347.39 r180 bottom value=0.51 (schematic designator R34)
R34_C "CRM0805-FX-R510ELF" 0805L 7694.61,1347.39 r180 bottom value=0.51 (schematic designator R34)
R35_A "CRM0805-FX-R510ELF" 0805L 1893.5,1636.5 r180 bottom value=0.51 (schematic designator R35)
R35_B "CRM0805-FX-R510ELF" 0805L 4793.5,1636.5 r180 bottom value=0.51 (schematic designator R35)
R35_C "CRM0805-FX-R510ELF" 0805L 7693.5,1636.5 r180 bottom value=0.51 (schematic designator R35)
R36_A "CRM0805-FX-R510ELF" 0805L 1893.5,1561.5 r180 bottom value=0.51 (schematic designator R36)
R36_B "CRM0805-FX-R510ELF" 0805L 4793.5,1561.5 r180 bottom value=0.51 (schematic designator R36)
R36_C "CRM0805-FX-R510ELF" 0805L 7693.5,1561.5 r180 bottom value=0.51 (schematic designator R36)
R37 "CRCW04024K70JNED" 0402 7795,2030 r180 top value=4.7k
R38 "CRCW04024K70JNED" 0402 7740,2310 r180 top value=4.7k
SH-J1 "SPC02SYAN" SPC02SYAN 5045,2498.67 r90 top value=1x2
SH-J2 "SPC02SYAN" SPC02SYAN 5150,2498.97 r90 top value=1x2
TP1 "PSE_3.3V" Keystone5000 3750,2560 r90 top
TP2 "VPWR" Keystone5000 2100,2250 r90 top
TP3 "GND" Keystone5001 1500,2250 r90 top
TP4 "GND" Keystone5001 3750,2395 r90 top
TP5 "3.3V_ISO" Keystone5000 8450,2150 r90 top
TP6 "RESET" Keystone5003 8300,2350 r90 top
TP7 "OSS" Keystone5003 8450,2350 r90 top
TP8 "INT" Keystone5003 8600,2350 r90 top
TP9 "SDA" Keystone5003 8450,2550 r90 top
TP10 "SCL" Keystone5003 8300,2550 r90 top
TP11 "PSE_RST" Keystone5002 5800,2550 r90 top
TP12 "PSE_OSS" Keystone5002 5350,2550 r90 top
TP13 "PSE_INT" Keystone5002 5500,2550 r90 top
TP14 "GND" Keystone5001 5650,2550 r90 top
TP15 "GND_ISO" Keystone5001 8600,2150 r90 top
TP16 "PSE_SCL" Keystone5002 6250,2550 r90 top
TP17 "PSE_SDAI" Keystone5002 5950,2550 r90 top
TP18 "PSE_SDAO" Keystone5002 6100,2550 r90 top
TP19 "GND" Keystone5001 7535,2075 r90 top
U1 "LM5017MRX/NOPB" DDA0008B_N 3115,2260 r0 top
U2 "ISO7731FDBQ" DBQ0016A_N 7210,2200 r270 top
U3 "ISO7741DBQR" DBQ0016A_N 7965,2200 r270 top
U4 "SN74LVC1G07DCKR" DCK0005A_N 7794.41,2425.71 r90 top
U5_A "TPS2388RTQR" RTQ0056E 1470,1325 r0 top (schematic designator U5)
U5_B "TPS2388RTQR" RTQ0056E 4370,1325 r0 top (schematic designator U5)
U5_C "TPS2388RTQR" RTQ0056E 7270,1325 r0 top (schematic designator U5)
ZZ1 "This Assembly Note is for PCB labels only" AssemblyNoteLabel 60,4435 r0 top
ZZ2 "These assemblies are ESD sensitive, ESD precautions shall be observed." AssemblyNote 65,4210 r0 top
ZZ3 "These assemblies must be clean and free from flux and all contaminants. Use of no clean flux is not acceptable." AssemblyNote 65,4010 r0 top
ZZ4 "These assemblies must comply with workmanship standards IPC-A-610 Class 2, unless otherwise specified." AssemblyNote 60,3790 r0 top
ZZ5 "DO NOT TRIM CONNECTOR PINS on J4 and J5" AssemblyNote 60,3580 r0 top

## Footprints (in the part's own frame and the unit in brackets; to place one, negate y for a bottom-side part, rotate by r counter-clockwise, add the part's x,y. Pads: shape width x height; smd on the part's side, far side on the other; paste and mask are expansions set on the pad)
0402 [mm] "0402 from SM-752 data"
  rect 0.8x0.6 smd: 1(-0.6,0) 2(0.6,0)
  silkscreen extent -1.22,-0.52 1.22,0.52, body extent -0.55,-0.3 0.55,0.3, height 0.6
0603 [mm] "0603 from SM-752 data"
  rect 1x0.95 smd: 1(-0.8,0) 2(0.8,0)
  silkscreen extent -1.52,-0.69 1.52,0.69, body extent -0.87,-0.47 0.87,0.47, height 1
0805_HV [mil] "0805 with 30mil clearance between pads"
  rect 50x63 smd: 1(-40,0) 2(40,0)
  silkscreen extent -74,-40 74,40, body extent -43,-29 43,29, height 57
0805L [mm] "0805 from SM-752 data"
  rect 1.1x1.4 smd: 1(-0.75,0) 2(0.75,0)
  body extent -1.1,-0.72 1.1,0.72, height 1.45
1206 [mm] "1206 from SM-752 data"
  rect 1.3x1.85 smd: 1(-1.45,0) 2(1.45,0)
  silkscreen extent -2.4,-1.21 2.4,1.21, body extent -1.7,-0.9 1.7,0.9, height 1.35
AssemblyNote [mil] "Assembly Note"
AssemblyNoteLabel [mil] "Assembly Note for PCB Labels"
CE_Mark_5mm [mil] "Minimum text height for CE Mark"
  silkscreen extent -138,-98 138,98
DBQ0016A_N [mm] "SOP, 16-Leads, Body 4.9x3.9mm, Pitch 0.635mm, IPC Medium Density"
  oval 1.45x0.4 smd: 1(-2.725,2.222) 2(-2.725,1.587) 3(-2.725,0.952) 4(-2.725,0.317) 5(-2.725,-0.318) 6(-2.725,-0.953) 7(-2.725,-1.588) 8(-2.725,-2.223) 9(2.725,-2.222) 10(2.725,-1.587) 11(2.725,-0.952) 12(2.725,-0.317) 13(2.725,0.318) 14(2.725,0.953) 15(2.725,1.588) 16(2.725,2.223)
  silkscreen extent -3.35,-2.5 1.1,2.68, body extent -3.01,-2.45 3.01,2.45, height 1.63
DCK0005A_N [mm] "SOT353, 5-Leads, Body 2x1.3mm, Pitch 0.65mm, Lead Span 2.1mm, IPC Medium Density"
  rrect25% 0.85x0.4 smd: 1(-1.125,0.65) 2(-1.125,0) 3(-1.125,-0.65) 4(1.125,-0.65) 5(1.125,0.65)
  silkscreen extent -1.48,-1.02 0.55,1.1, body extent -1.14,-1 1.14,1, height 0.95
DDA0008B_N [mm] "SOIC, 8-Leads, Body 4.9x3.9mm, Pitch 1.27mm, Exposed Pad, IPC Medium Density"
  rrect17% 1.45x0.6 smd: 1(-2.725,1.905) 2(-2.725,0.635) 3(-2.725,-0.635) 4(-2.725,-1.905) 5(2.725,-1.905) 6(2.725,-0.635) 7(2.725,0.635) 8(2.725,1.905)
  rrect7% 2.95x4.9 smd paste-1.5 mask-1.5: 9(0,0)
  rrect4% 2.71x3.4 on Top Paste: 9(0,0)
  rrect4% 2.71x3.4 on Top Solder: 9(0,0)
  silkscreen extent -3.5,-2.5 1.1,2.5, body extent -3.01,-2.45 3.01,2.45, height 1.57
DNH0008A_NV [mm] "8 pin VSONP, 0.65 mm pitch"
  rrect50% 0.7x0.4 smd paste-0.05 mask-0.05: 1(-1.55,0.975) 2(-1.55,0.325) 3(-1.55,-0.325) 4(-1.55,-0.975) 5(1.55,-0.975) 6(1.55,-0.325) 7(1.55,0.325) 8(1.55,0.975)
  rrect14% 0.705x1.125 on Top Paste: 9(-0.208,0.662) 9(-0.208,-0.663) 9(0.697,0.662) 9(0.697,-0.663)
  rrect6% 1.775x2.45 on Top Solder: 9(0.327,0)
  rrect4% 2.51x2.55 smd paste-1.5 mask-1.5: 9(0.645,0)
  rect 0.5x0.3 on Top Solder: 9(1.175,0.975) 9(1.175,-0.325) 9(1.175,0.325) 9(1.175,-0.975)
  silkscreen extent -1.62,-1.7 1.62,1.7, body extent -1.65,-1.65 1.65,1.66, height 0.91
FCC_disclaimer [mil]
Fiducial10-20 [mm]
  round 1 smd mask+0.5: 1(0,0)
  Top Layer keep-out circle w1.178: c0,0 r0.5
FP-GCM1555C1H121FA16D_0402-MFG [mm]
  rrect25% 0.4x0.5 smd paste+0 mask+0: 1(-0.4,0) 2(0.4,0)
  body extent -0.7,-0.38 0.7,0.38, height 0.25
Keystone5000 [mil] "For Keystone 500x miniature loop terminals"
  round 80 hole 40: 1(0,0)
  silkscreen extent -52,-52 52,52, body extent -49,-49 49,49, height 182
Keystone5001 [mil] "For Keystone 500x miniature loop terminals"
  round 80 hole 40: 1(0,0)
  silkscreen extent -52,-52 52,52, body extent -49,-49 49,49, height 182
Keystone5002 [mil] "For Keystone 500x miniature loop terminals"
  round 80 hole 40: 1(0,0)
  silkscreen extent -52,-52 52,52, body extent -49,-49 49,49, height 182
Keystone5003 [mil] "For Keystone 500x miniature loop terminals"
  round 80 hole 40: 1(0,0)
  silkscreen extent -52,-52 52,52, body extent -49,-49 49,49, height 182
Label_650x200 [mil] "Thermal Transfer Label"
  round 1 on Mech13: 0(0,0)
  silkscreen extent -325,-100 325,100, body extent -325,-100 325,100, height 1
Net-Tie_10milWide_30milLong [mil] "10mil net tie, no solder mask opening, no solder paste"
  rect 30x10 smd paste-5 mask-5: 1(-15,0) 2(15,0)
RTQ0056E [mm] "QFN, 56-Leads, Body 8x8mm, Pitch 0.5mm, Thermal Pad 5.7x5.7mm, TI Recommended"
  rrect42% 0.6x0.24 smd: 1(-3.9,3.25) 2(-3.9,2.75) 3(-3.9,2.25) 4(-3.9,1.75) 5(-3.9,1.25) 6(-3.9,0.75) 7(-3.9,0.25) 8(-3.9,-0.25) 9(-3.9,-0.75) 10(-3.9,-1.25) 11(-3.9,-1.75) 12(-3.9,-2.25) 13(-3.9,-2.75) 14(-3.9,-3.25) 29(3.9,-3.25) 30(3.9,-2.75) 31(3.9,-2.25) 32(3.9,-1.75) 33(3.9,-1.25) 34(3.9,-0.75) 35(3.9,-0.25) 36(3.9,0.25) 37(3.9,0.75) 38(3.9,1.25) 39(3.9,1.75) 40(3.9,2.25) 41(3.9,2.75) 42(3.9,3.25)
  rrect42% 0.24x0.6 smd: 15(-3.25,-3.9) 16(-2.75,-3.9) 17(-2.25,-3.9) 18(-1.75,-3.9) 19(-1.25,-3.9) 20(-0.75,-3.9) 21(-0.25,-3.9) 22(0.25,-3.9) 23(0.75,-3.9) 24(1.25,-3.9) 25(1.75,-3.9) 26(2.25,-3.9) 27(2.75,-3.9) 28(3.25,-3.9) 43(3.25,3.9) 44(2.75,3.9) 45(2.25,3.9) 46(1.75,3.9) 47(1.25,3.9) 48(0.75,3.9) 49(0.25,3.9) 50(-0.25,3.9) 51(-0.75,3.9) 52(-1.25,3.9) 53(-1.75,3.9) 54(-2.25,3.9) 55(-2.75,3.9) 56(-3.25,3.9)
  rrect9% 1.15x1.15 on Top Paste: 57(-2.025,-2.025) 57(-2.025,-0.675) 57(-2.025,0.675) 57(-2.025,2.025) 57(-0.675,-2.025) 57(-0.675,-0.675) 57(-0.675,0.675) 57(-0.675,2.025) 57(0.675,-2.025) 57(0.675,-0.675) 57(0.675,0.675) 57(0.675,2.025) 57(2.025,-2.025) 57(2.025,-0.675) 57(2.025,0.675) 57(2.025,2.025)
  rrect2% 5.7x5.7 smd paste-3: 57(0,0)
  silkscreen extent -4.22,-4.23 4.22,4.23, body extent -4,-4 4,4, height 1
SOT-143-4 [mm] "Littelfuse"
  rect 1.4x1.2 smd: 1(-1.1,0.9)
  rect 1.4x1 smd: 2(-1.1,-0.8) 3(1.1,-0.8) 4(1.1,1.1)
  silkscreen extent -1.22,1.8 -1.02,2.01, body extent -0.7,-1.37 0.7,1.67, height 1.23
SPC02SYAN [mil] "SULLINS"
  round 1 on Mech3: 0(0,0)
  body extent -98,-47 99,47, height 366
TI_Stacked_Overlay_Small [mil]
  silkscreen extent -418,-98 418,98
TSW-102-07-G-D [mm] "Samtec 100mil, 2x2, 230 mil above insulator"
  rrect6% 1.65x1.65 hole 1.016: 1(-1.27,-1.27)
  round 1.65 hole 1.016: 2(-1.27,1.27) 3(1.27,-1.27) 4(1.27,1.27)
  silkscreen extent -3.56,-2.54 2.54,2.54, body extent -2.54,-2.54 2.54,2.54, height 8.38
TSW-108-07-G-D [mm] "Samtec 100mil, 2x8, 230 mil above insulator"
  rrect6% 1.65x1.65 hole 1.016: 1(-8.89,-1.27)
  round 1.65 hole 1.016: 2(-8.89,1.27) 3(-6.35,-1.27) 4(-6.35,1.27) 5(-3.81,-1.27) 6(-3.81,1.27) 7(-1.27,-1.27) 8(-1.27,1.27) 9(1.27,-1.27) 10(1.27,1.27) 11(3.81,-1.27) 12(3.81,1.27) 13(6.35,-1.27) 14(6.35,1.27) 15(8.89,-1.27) 16(8.89,1.27)
  silkscreen extent -11.18,-2.54 10.16,2.54, body extent -10.16,-2.54 10.16,2.54, height 8.38
TSW-110-07-G-S [mm] "Samtec 100mil, 1x10, 230 mil above insulator"
  rrect6% 1.65x1.65 hole 1.016: 1(-11.43,0)
  round 1.65 hole 1.016: 2(-8.89,0) 3(-6.35,0) 4(-3.81,0) 5(-1.27,0) 6(1.27,0) 7(3.81,0) 8(6.35,0) 9(8.89,0) 10(11.43,0)
  silkscreen extent -12.7,-1.27 12.7,1.65, body extent -12.7,-1.27 12.7,1.27, height 8.38
TSW-112-07-G-D [mm] "Samtec 100mil, 2x12, 230 mil above insulator"
  rrect6% 1.65x1.65 hole 1.016: 1(-13.97,-1.27)
  round 1.65 hole 1.016: 2(-13.97,1.27) 3(-11.43,-1.27) 4(-11.43,1.27) 5(-8.89,-1.27) 6(-8.89,1.27) 7(-6.35,-1.27) 8(-6.35,1.27) 9(-3.81,-1.27) 10(-3.81,1.27) 11(-1.27,-1.27) 12(-1.27,1.27) 13(1.27,-1.27) 14(1.27,1.27) 15(3.81,-1.27) 16(3.81,1.27) 17(6.35,-1.27) 18(6.35,1.27) 19(8.89,-1.27) 20(8.89,1.27) 21(11.43,-1.27) 22(11.43,1.27) 23(13.97,-1.27) 24(13.97,1.27)
  silkscreen extent -16.27,-2.54 15.24,2.54, body extent -15.24,-2.54 15.24,2.54, height 8.38
WE-TPC_6823 [mm] "Wurth"
  round 0.9 smd: 1(0,3.2) 2(0,-3.15)
  Top Layer region: -3.65,1.05 -2.5,1.05 -2.485,1.055 -1.743,2.062 -0.626,2.626 0.626,2.626 1.743,2.062 2.485,1.055 2.485,1.055 2.5,1.05 3.65,1.05 3.65,3.65 -3.65,3.65
  Top Layer region: 3.65,-1.05 2.5,-1.05 2.485,-1.055 1.743,-2.062 0.626,-2.626 -0.626,-2.626 -1.743,-2.062 -2.485,-1.055 -2.485,-1.055 -2.5,-1.05 -3.65,-1.05 -3.65,-3.65 3.65,-3.65
  body extent -3.5,-3.5 3.5,3.5, height 2.5
WEEE_Minimum [mil] "WEEElie bin"
  silkscreen extent -95,-172 99,104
